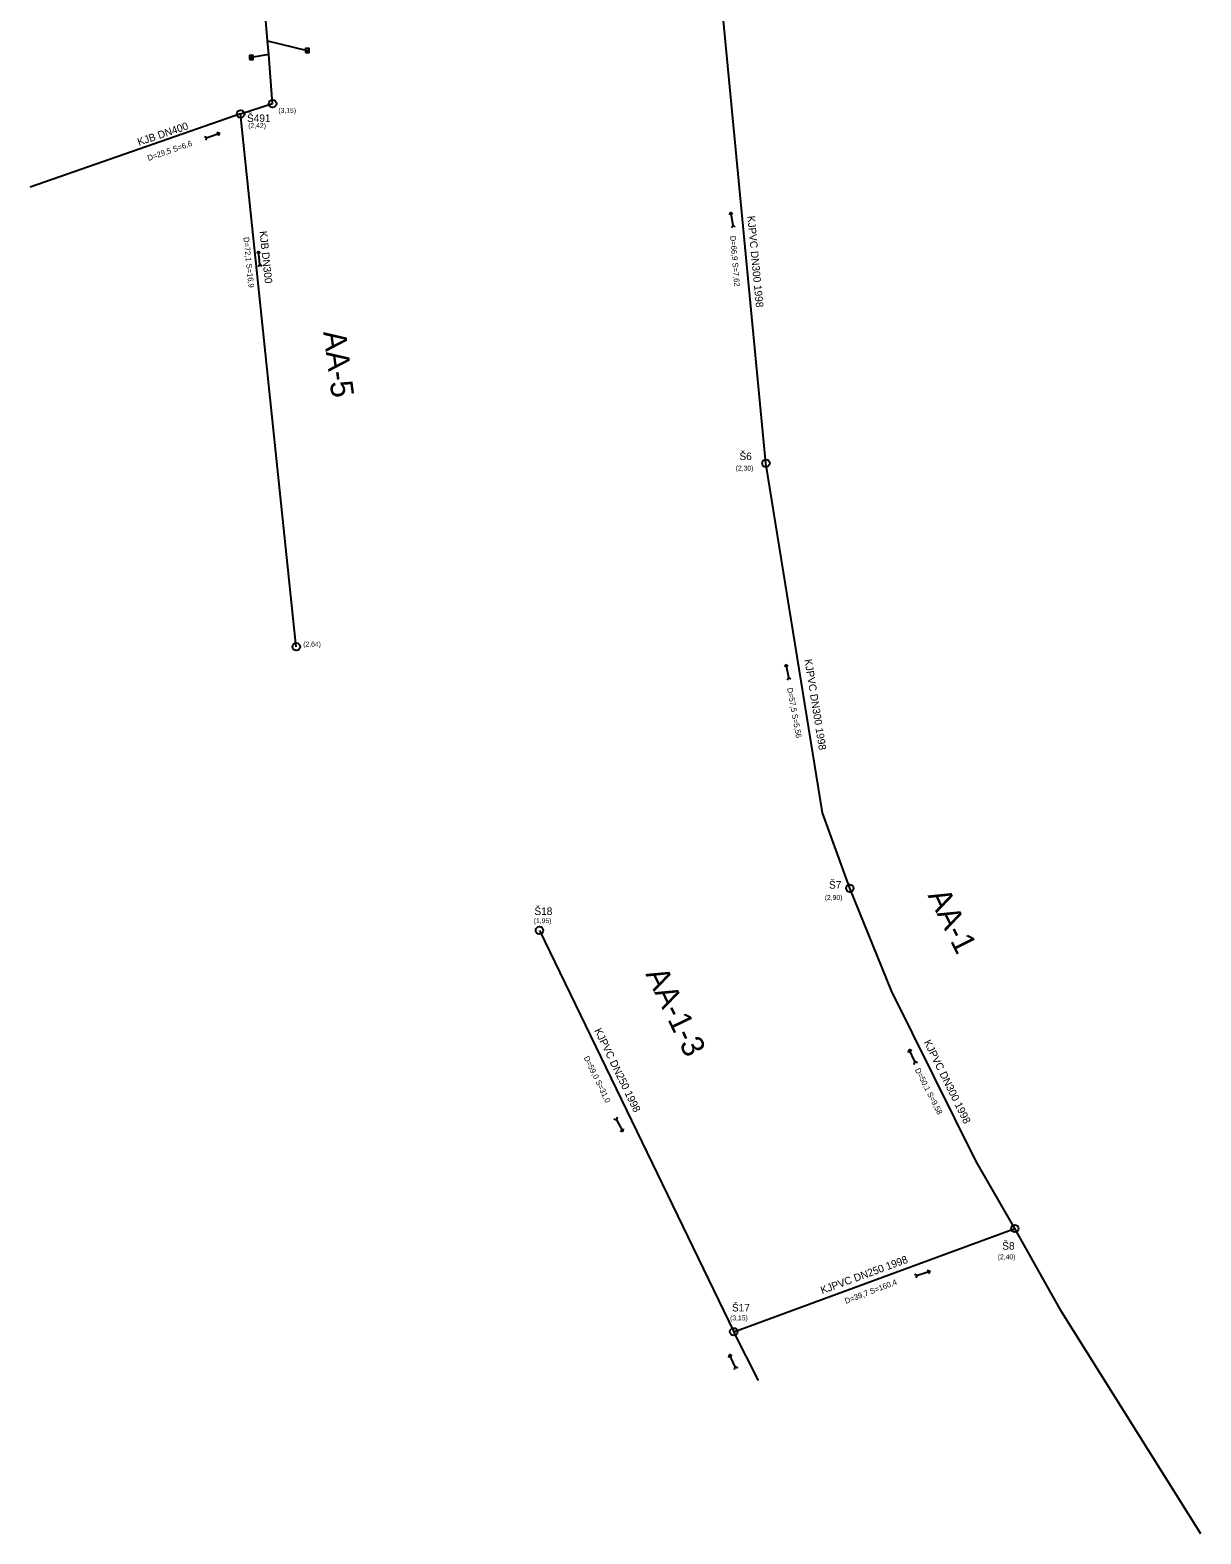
# Model space of a CAD drawing. Extents: x -539706 to -539225, y -1156458 to -1155912.
# Drawn here: x -539659.4 to -539504.3, y -1156458.1 to -1156258.9 of the extents above; entities that cross this region are included whole.
import ezdxf

# ---------------------------------------------------------------- set-up
doc = ezdxf.new("R2010")
doc.units = 0
for name, color, linetype in [('Vrstva 17', 7, 'Continuous'), ('Vrstva 29', 7, 'Continuous'), ('Vrstva 34', 7, 'Continuous'), ('Vrstva 39', 7, 'Continuous'), ('Vrstva 54', 7, 'Continuous'), ('Vrstva 57', 7, 'Continuous'), ('Vrstva 59', 7, 'Continuous'), ('Vrstva 60', 7, 'Continuous'), ('Vrstva 7', 7, 'Continuous'), ('Vrstva 8', 7, 'Continuous'), ('Vrstva 9', 7, 'Continuous')]:
    doc.layers.add(name, color=color, linetype=linetype)

msp = doc.modelspace()

# ---------------------------------------------------------------- linework, layer by layer
at = {"layer": 'Vrstva 17'}
for p, q in [((-539627.96, -1156260.31), (-539622.68, -1156261.59)), ((-539627.8, -1156262.14), (-539630.11, -1156262.53))]:
    msp.add_line(p, q, dxfattribs=at)
at = {"layer": 'Vrstva 29'}
for centre in [(-539627.28, -1156268.64), (-539631.52, -1156270), (-539561.93, -1156316.27), (-539624.14, -1156340.59), (-539550.81, -1156372.58), (-539591.93, -1156378.17), (-539528.95, -1156417.66), (-539566.19, -1156431.34)]:
    msp.add_circle(centre, 0.5, dxfattribs=at)
at = {"layer": 'Vrstva 34'}
for p, q in [((-539622.93, -1156261.59), (-539622.43, -1156261.59)), ((-539630.36, -1156262.53), (-539629.86, -1156262.53))]:
    msp.add_line(p, q, dxfattribs=at)
for points in [[(-539630.36, -1156262.781), (-539629.86, -1156262.78), (-539629.86, -1156262.28), (-539630.359, -1156262.28)], [(-539622.93, -1156261.841), (-539622.43, -1156261.84), (-539622.43, -1156261.34), (-539622.929, -1156261.34)]]:
    msp.add_lwpolyline(points, close=True, dxfattribs=at)
at = {"layer": 'Vrstva 39'}
for p, q in [((-539636.315, -1156272.997), (-539635.942, -1156273.117)), ((-539636.156, -1156273.446), (-539635.942, -1156273.117)), ((-539635.942, -1156273.117), (-539634.289, -1156272.529)), ((-539634.657, -1156272.412), (-539634.289, -1156272.529)), ((-539634.501, -1156272.848), (-539634.289, -1156272.529)), ((-539566.746, -1156283.357), (-539566.568, -1156283.014)), ((-539566.274, -1156284.744), (-539566.568, -1156283.014)), ((-539566.289, -1156283.278), (-539566.568, -1156283.014)), ((-539566.456, -1156285.091), (-539566.274, -1156284.744)), ((-539565.985, -1156285.012), (-539566.274, -1156284.744)), ((-539629.345, -1156288.502), (-539629.144, -1156288.172)), ((-539628.965, -1156289.917), (-539629.144, -1156288.172)), ((-539628.884, -1156288.454), (-539629.144, -1156288.172)), ((-539629.169, -1156290.251), (-539628.965, -1156289.917)), ((-539628.694, -1156290.204), (-539628.965, -1156289.917)), ((-539559.417, -1156343.268), (-539559.248, -1156342.921)), ((-539558.905, -1156344.641), (-539559.248, -1156342.921)), ((-539558.962, -1156343.177), (-539559.248, -1156342.921)), ((-539559.077, -1156344.994), (-539558.905, -1156344.641)), ((-539558.609, -1156344.901), (-539558.905, -1156344.641)), ((-539543.028, -1156394.321), (-539542.945, -1156393.944)), ((-539542.21, -1156395.537), (-539542.945, -1156393.944)), ((-539542.607, -1156394.126), (-539542.945, -1156393.944)), ((-539542.295, -1156395.92), (-539542.21, -1156395.537)), ((-539541.862, -1156395.721), (-539542.21, -1156395.537)), ((-539582.07, -1156403.113), (-539581.711, -1156403.274)), ((-539581.65, -1156402.887), (-539581.711, -1156403.274)), ((-539581.711, -1156403.274), (-539580.878, -1156404.818)), ((-539581.226, -1156404.657), (-539580.878, -1156404.818)), ((-539580.818, -1156404.436), (-539580.878, -1156404.818)), ((-539542.23, -1156423.715), (-539541.861, -1156423.849)), ((-539541.861, -1156423.849), (-539540.186, -1156423.329)), ((-539540.549, -1156423.197), (-539540.186, -1156423.329)), ((-539540.411, -1156423.64), (-539540.186, -1156423.329)), ((-539542.089, -1156424.171), (-539541.861, -1156423.849)), ((-539566.826, -1156434.741), (-539566.74, -1156434.364)), ((-539566.016, -1156435.962), (-539566.74, -1156434.364)), ((-539566.403, -1156434.549), (-539566.74, -1156434.364)), ((-539566.103, -1156436.344), (-539566.016, -1156435.962)), ((-539565.669, -1156436.148), (-539566.016, -1156435.962))]:
    msp.add_line(p, q, dxfattribs=at)
at = {"layer": 'Vrstva 8'}
for p, q in [((-539561.93, -1156316.27), (-539568.33, -1156249.61)), ((-539627.96, -1156260.31), (-539628.69, -1156251.67)), ((-539627.8, -1156262.14), (-539627.96, -1156260.31)), ((-539627.28, -1156268.64), (-539627.8, -1156262.14)), ((-539591.93, -1156378.17), (-539566.19, -1156431.34)), ((-539566.19, -1156431.34), (-539528.95, -1156417.66)), ((-539562.89, -1156437.78), (-539566.19, -1156431.34))]:
    msp.add_line(p, q, dxfattribs=at)
for points in [[(-539550.81, -1156372.58), (-539554.45, -1156362.6), (-539561.93, -1156316.27)], [(-539528.95, -1156417.66), (-539534.14, -1156408.71), (-539545.29, -1156386.17), (-539550.81, -1156372.58)], [(-539504.3, -1156458.12), (-539522.72, -1156428.72), (-539528.95, -1156417.66)]]:
    msp.add_lwpolyline(points, dxfattribs=at)
at = {"layer": 'Vrstva 9'}
for p, q in [((-539631.52, -1156270), (-539659.41, -1156279.69)), ((-539631.52, -1156270), (-539627.28, -1156268.64)), ((-539624.14, -1156340.59), (-539631.52, -1156270))]:
    msp.add_line(p, q, dxfattribs=at)

# ---------------------------------------------------------------- texts
at = {"layer": 'Vrstva 54'}
for s, rotation, p in [('D=29,5 S=6,6', 19.15909, (-539643.716, -1156276.231)), ('D=66,9 S=7,62', 274.8493, (-539566.678, -1156286.179)), ('D=72,1 S=16,9', 275.95118, (-539631.148, -1156286.351)), ('D=57,5 S=5,56', 280.33634, (-539559.133, -1156346.084)), ('D=59,0 S=31,0', 295.96853, (-539586.09, -1156395.024)), ('D=50,1 S=9,58', 296.97723, (-539542.216, -1156396.638)), ('D=39,7 S=160,4', 20.86947, (-539551.321, -1156427.645))]:
    msp.add_text(s, height=0.75, rotation=rotation, dxfattribs=at).set_placement(p)
at = {"layer": 'Vrstva 57'}
for s, p in [('Š491', (-539630.673, -1156271.068)), ('Š6', (-539565.435, -1156315.853)), ('Š7', (-539553.571, -1156372.636)), ('Š18', (-539592.599, -1156376.123)), ('Š8', (-539530.621, -1156420.465)), ('Š17', (-539566.428, -1156428.648))]:
    msp.add_text(s, height=1, dxfattribs=at).set_placement(p)
at = {"layer": 'Vrstva 59'}
for s, p in [('(3,15)', (-539626.516, -1156269.852)), ('(2,42)', (-539630.503, -1156271.869)), ('(2,30) ', (-539565.933, -1156317.255)), ('(2,64)', (-539623.227, -1156340.566)), ('(2,90) ', (-539554.136, -1156374.136)), ('(1,95) ', (-539592.688, -1156377.203)), ('(2,40) ', (-539531.218, -1156421.737)), ('(3,15) ', (-539566.678, -1156429.828))]:
    msp.add_text(s, height=0.65, dxfattribs=at).set_placement(p)
at = {"layer": 'Vrstva 60'}
for s, rotation, p in [('AA-5', 277.45906, (-539620.578, -1156298.886)), ('AA-1', 296.3205, (-539540.53, -1156373.531)), ('AA-1-3', 295.83197, (-539577.917, -1156383.932))]:
    msp.add_text(s, height=3, rotation=rotation, dxfattribs=at).set_placement(p)
at = {"layer": 'Vrstva 7'}
for s, rotation, p in [('KJB DN400', 18.58524, (-539644.986, -1156274.229)), ('KJPVC DN300 1998', 275.48848, (-539564.4, -1156283.545)), ('KJB DN300', 275.9683, (-539629.021, -1156285.556)), ('KJPVC DN300 1998', 279.17431, (-539556.833, -1156342.301)), ('KJPVC DN250 1998', 295.83367, (-539584.688, -1156391.412)), ('KJPVC DN300 1998', 296.32067, (-539541.045, -1156392.967)), ('KJPVC DN250 1998', 20.17416, (-539554.473, -1156426.357))]:
    msp.add_text(s, height=1, rotation=rotation, dxfattribs=at).set_placement(p)

doc.saveas('drawing.dxf')
